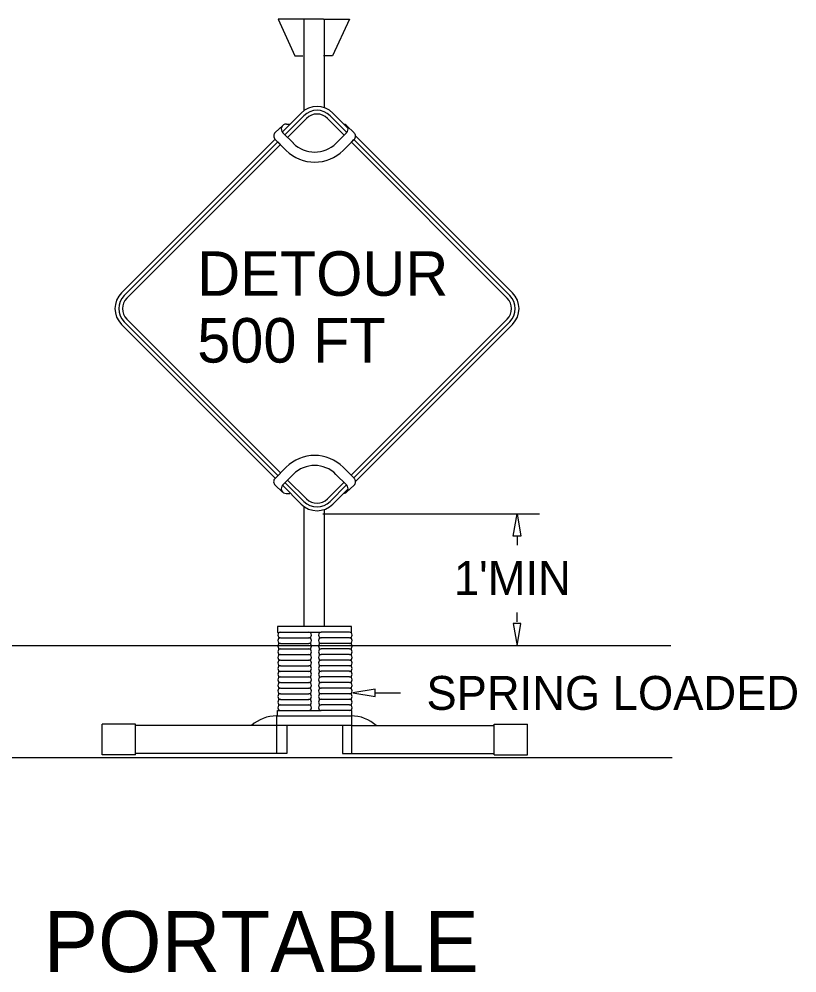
# Model space of a CAD drawing. Extents: x 12.65 to 19.62, y 5.94 to 15.74.
# Drawn here: x 14.024 to 15.401, y 12.626 to 14.315 of the extents above; entities that cross this region are included whole.
import ezdxf

# ---------------------------------------------------------------- set-up
doc = ezdxf.new("R2010")
doc.units = 0
for name, color, linetype in [('DETL-DIMS', 7, 'Continuous'), ('DETL-LINE', 7, 'Continuous'), ('DETL-NOTE', 7, 'Continuous'), ('DETL-TITL', 7, 'Continuous')]:
    doc.layers.add(name, color=color, linetype=linetype)

msp = doc.modelspace()

# ---------------------------------------------------------------- linework, layer by layer
at = {"layer": 'DETL-DIMS'}
for p, q in [((14.5617, 13.4389), (14.9454, 13.4389)), ((14.9058, 13.3993), (14.9058, 13.383)), ((14.9058, 13.2478), (14.9058, 13.2642)), ((14.6548, 13.1218), (14.6994, 13.1218))]:
    msp.add_line(p, q, dxfattribs=at)
for points in [[(14.9124, 13.3993), (14.8992, 13.3993), (14.9058, 13.4389)], [(14.9124, 13.2445), (14.8992, 13.2445), (14.9058, 13.2049)], [(14.6548, 13.1152), (14.6548, 13.1284), (14.6152, 13.1218)]]:
    msp.add_lwpolyline(points, close=True, dxfattribs=at)
at = {"layer": 'DETL-LINE'}
for p, q in [((14.5286, 14.3146), (14.4826, 14.3146)), ((14.4826, 14.3146), (14.5124, 14.2494)), ((14.5629, 14.3146), (14.5266, 14.3146)), ((14.5286, 14.1523), (14.5286, 14.3146)), ((14.5629, 14.3146), (14.609, 14.3146)), ((14.5649, 14.1574), (14.5649, 14.3146)), ((14.609, 14.3146), (14.5791, 14.2494)), ((14.5124, 14.2494), (14.5266, 14.2494)), ((14.5791, 14.2494), (14.5629, 14.2494)), ((14.5235, 14.1481), (14.4901, 14.1145)), ((14.5282, 14.1434), (14.4947, 14.1098)), ((14.4993, 14.1051), (14.5329, 14.1386)), ((14.5703, 14.1387), (14.5703, 14.1386)), ((14.5703, 14.1386), (14.5997, 14.1092)), ((14.6044, 14.1139), (14.575, 14.1434)), ((14.6066, 14.1211), (14.5797, 14.1481)), ((14.4909, 14.1261), (14.4777, 14.1138)), ((14.4973, 14.1287), (14.5043, 14.1287)), ((14.6047, 14.1255), (14.6173, 14.1135)), ((14.4774, 14.1019), (14.2056, 13.83)), ((14.4971, 14.0821), (14.4775, 14.1017)), ((14.5097, 14.0947), (14.491, 14.1135)), ((14.6041, 14.1135), (14.5853, 14.0947)), ((14.6173, 14.1016), (14.5979, 14.0821)), ((14.6124, 14.0966), (14.6171, 14.1013)), ((14.8929, 13.8253), (14.6171, 14.1013)), ((14.6171, 14.1013), (14.8929, 13.8253)), ((14.8929, 13.8253), (14.6171, 14.1013)), ((14.6171, 14.1013), (14.8929, 13.8253)), ((14.6171, 14.1013), (14.8929, 13.8253)), ((14.8976, 13.83), (14.6198, 14.1079)), ((14.2103, 13.8253), (14.4821, 14.0972)), ((14.4867, 14.0925), (14.2149, 13.8207)), ((14.4821, 14.0972), (14.4867, 14.0925)), ((14.8883, 13.8207), (14.6124, 14.0966)), ((14.6124, 14.0966), (14.8883, 13.8207)), ((14.8883, 13.8207), (14.6124, 14.0966)), ((14.6124, 14.0966), (14.8883, 13.8207)), ((14.8883, 13.8207), (14.6124, 14.0966)), ((14.487, 13.5112), (14.2149, 13.7833)), ((14.6121, 13.5071), (14.8883, 13.7833)), ((14.8883, 13.7833), (14.6121, 13.5071)), ((14.6121, 13.5071), (14.8883, 13.7833)), ((14.8883, 13.7833), (14.6121, 13.5071)), ((14.6121, 13.5071), (14.8883, 13.7833)), ((14.8883, 13.7833), (14.8883, 13.7833)), ((14.2056, 13.7739), (14.4776, 13.5019)), ((14.2102, 13.7786), (14.2103, 13.7786)), ((14.2103, 13.7786), (14.4823, 13.5065)), ((14.6167, 13.5024), (14.8929, 13.7786)), ((14.8929, 13.7786), (14.6167, 13.5024)), ((14.8929, 13.7786), (14.6167, 13.5024)), ((14.62, 13.4962), (14.8976, 13.7739)), ((14.497, 13.5212), (14.4773, 13.5015)), ((14.6175, 13.5016), (14.5978, 13.5212)), ((14.5096, 13.5086), (14.4909, 13.4899)), ((14.4949, 13.4939), (14.5282, 13.4606)), ((14.5329, 13.4653), (14.4996, 13.4986)), ((14.5995, 13.4945), (14.5703, 13.4653)), ((14.6039, 13.4899), (14.5852, 13.5086)), ((14.4908, 13.4769), (14.4775, 13.4895)), ((14.4903, 13.4892), (14.5235, 13.4559)), ((14.575, 13.4606), (14.6041, 13.4898)), ((14.5797, 13.4559), (14.6066, 13.4829)), ((14.6037, 13.4769), (14.6173, 13.4895)), ((14.4972, 13.4747), (14.5034, 13.4747)), ((14.5329, 13.4653), (14.5329, 13.4653)), ((14.5286, 13.2384), (14.5286, 13.4516)), ((14.5649, 13.2384), (14.5649, 13.4466)), ((14.6125, 13.239), (14.4819, 13.239)), ((14.4819, 13.239), (14.4819, 13.2289)), ((14.4819, 13.2289), (14.4872, 13.2291)), ((14.4872, 13.2291), (14.537, 13.2291)), ((14.537, 13.2291), (14.5592, 13.2291)), ((14.609, 13.2291), (14.5592, 13.2291)), ((14.6125, 13.2289), (14.609, 13.2291)), ((14.6125, 13.2289), (14.6125, 13.239)), ((13.0783, 13.2055), (15.1784, 13.2055)), ((14.4872, 13.2193), (14.537, 13.2193)), ((14.4872, 13.2093), (14.537, 13.2093)), ((14.609, 13.2193), (14.5592, 13.2193)), ((14.609, 13.2093), (14.5592, 13.2093)), ((14.9058, 13.2082), (14.9058, 13.2082)), ((14.9058, 13.2082), (14.9058, 13.2082)), ((14.4872, 13.1995), (14.537, 13.1995)), ((14.4872, 13.1895), (14.537, 13.1895)), ((14.609, 13.1995), (14.5592, 13.1995)), ((14.609, 13.1895), (14.5592, 13.1895)), ((14.4872, 13.1797), (14.537, 13.1797)), ((14.609, 13.1797), (14.5592, 13.1797)), ((14.4872, 13.1697), (14.537, 13.1697)), ((14.4872, 13.1599), (14.537, 13.1599)), ((14.609, 13.1697), (14.5592, 13.1697)), ((14.609, 13.1599), (14.5592, 13.1599)), ((14.4872, 13.1499), (14.537, 13.1499)), ((14.4872, 13.1401), (14.537, 13.1401)), ((14.609, 13.1499), (14.5592, 13.1499)), ((14.609, 13.1401), (14.5592, 13.1401)), ((14.4872, 13.1301), (14.537, 13.1301)), ((14.609, 13.1301), (14.5592, 13.1301)), ((14.4872, 13.1203), (14.537, 13.1203)), ((14.4872, 13.1103), (14.537, 13.1103)), ((14.609, 13.1203), (14.5592, 13.1203)), ((14.609, 13.1103), (14.5592, 13.1103)), ((14.4815, 13.0904), (14.4872, 13.0905)), ((14.4815, 13.0807), (14.4815, 13.0904)), ((14.4872, 13.1005), (14.537, 13.1005)), ((14.4872, 13.0905), (14.537, 13.0905)), ((14.537, 13.0905), (14.5592, 13.0905)), ((14.609, 13.1005), (14.5592, 13.1005)), ((14.609, 13.0905), (14.5592, 13.0905)), ((14.6129, 13.0904), (14.609, 13.0905)), ((14.6129, 13.0904), (14.6129, 13.0807)), ((14.48, 13.0809), (14.612, 13.0809)), ((14.48, 13.0809), (14.48, 13.0644)), ((14.6129, 13.0807), (14.4815, 13.0807)), ((14.6125, 13.0806), (14.6125, 13.064)), ((14.2302, 13.0662), (14.1713, 13.0662)), ((14.1713, 13.012), (14.1713, 13.0662)), ((14.2302, 13.012), (14.2302, 13.0662)), ((14.4831, 13.064), (14.2302, 13.064)), ((14.48, 13.0644), (14.612, 13.0644)), ((14.48, 13.0644), (14.48, 13.0142)), ((14.4981, 13.064), (14.4981, 13.0142)), ((14.5967, 13.064), (14.5967, 13.0142)), ((14.6125, 13.064), (14.8654, 13.064)), ((14.6125, 13.064), (14.6125, 13.0142)), ((14.8654, 13.0662), (14.9244, 13.0662)), ((14.8654, 13.012), (14.8654, 13.0662)), ((14.9244, 13.012), (14.9244, 13.0662)), ((15.1805, 13.0067), (13.8687, 13.0067)), ((14.2302, 13.012), (14.1713, 13.012)), ((14.4981, 13.0142), (14.2302, 13.0142)), ((14.5967, 13.0142), (14.8654, 13.0142)), ((14.8654, 13.012), (14.9244, 13.012))]:
    msp.add_line(p, q, dxfattribs=at)
for centre, radius, start, end in [((14.5516, 14.12), 0.0397, 45, 135), ((14.5516, 14.12), 0.0331, 45, 135), ((14.5516, 14.12), 0.0265, 45, 135), ((14.4973, 14.1198), 0.00891, 90, 225.0258), ((14.5978, 14.1198), 0.00891, 314.9742, 81.781), ((14.4834, 14.1077), 0.00836, 132.9298, 225.0258), ((14.6114, 14.1075), 0.00836, 314.9742, 46.0534), ((14.5475, 14.1326), 0.0535, 225.0258, 314.9742), ((14.5475, 14.1326), 0.0713, 225.0258, 314.9742), ((14.2336, 13.802), 0.0397, 135, 225), ((14.2336, 13.802), 0.0331, 135, 225), ((14.2336, 13.802), 0.0265, 135, 225), ((14.8696, 13.802), 0.0265, 315, 45), ((14.8696, 13.802), 0.0331, 315, 45), ((14.8696, 13.802), 0.0397, 315, 45), ((14.5474, 13.4708), 0.0713, 45.0258, 134.9742), ((14.5474, 13.4708), 0.0535, 45.0258, 134.9742), ((14.4832, 13.4956), 0.00836, 134.9742, 226.7296), ((14.6116, 13.4956), 0.00836, 312.6558, 45.0258), ((14.4972, 13.4836), 0.00891, 134.9742, 270), ((14.5977, 13.4836), 0.00891, 270, 45.0258), ((14.5516, 13.484), 0.0331, 225, 315), ((14.5516, 13.484), 0.0265, 225, 315), ((14.5516, 13.484), 0.0397, 225, 315), ((14.4872, 13.2242), 0.00495, 90, 270), ((14.537, 13.2242), 0.00495, 270.0001, 89.9999), ((14.5592, 13.2242), 0.00495, 90.0001, 269.9999), ((14.609, 13.2242), 0.00495, 270, 90), ((14.4872, 13.2143), 0.00495, 90, 270), ((14.4872, 13.2044), 0.00495, 90, 270), ((14.537, 13.2143), 0.00495, 270.0001, 89.9999), ((14.537, 13.2044), 0.00495, 270.0001, 89.9999), ((14.5592, 13.2143), 0.00495, 90.0001, 269.9999), ((14.5592, 13.2044), 0.00495, 90.0001, 269.9999), ((14.609, 13.2143), 0.00495, 270, 90), ((14.609, 13.2044), 0.00495, 270, 90), ((14.4872, 13.1945), 0.00495, 90, 270), ((14.4872, 13.1846), 0.00495, 90, 270), ((14.537, 13.1945), 0.00495, 270.0001, 89.9999), ((14.537, 13.1846), 0.00495, 270.0001, 89.9999), ((14.5592, 13.1945), 0.00495, 90.0001, 269.9999), ((14.5592, 13.1846), 0.00495, 90.0001, 269.9999), ((14.609, 13.1945), 0.00495, 270, 90), ((14.609, 13.1846), 0.00495, 270, 90), ((14.4872, 13.1747), 0.00495, 90, 270), ((14.537, 13.1747), 0.00495, 270.0001, 89.9999), ((14.5592, 13.1747), 0.00495, 90.0001, 269.9999), ((14.609, 13.1747), 0.00495, 270, 90), ((14.4872, 13.1648), 0.00495, 90, 270), ((14.4872, 13.1549), 0.00495, 90, 270), ((14.537, 13.1648), 0.00495, 270.0001, 89.9999), ((14.537, 13.1549), 0.00495, 270.0001, 89.9999), ((14.5592, 13.1648), 0.00495, 90.0001, 269.9999), ((14.5592, 13.1549), 0.00495, 90.0001, 269.9999), ((14.609, 13.1648), 0.00495, 270, 90), ((14.609, 13.1549), 0.00495, 270, 90), ((14.4872, 13.145), 0.00495, 90, 270), ((14.4872, 13.1351), 0.00495, 90, 270), ((14.537, 13.145), 0.00495, 270.0001, 89.9999), ((14.537, 13.1351), 0.00495, 270.0001, 89.9999), ((14.5592, 13.145), 0.00495, 90.0001, 269.9999), ((14.5592, 13.1351), 0.00495, 90.0001, 269.9999), ((14.609, 13.145), 0.00495, 270, 90), ((14.609, 13.1351), 0.00495, 270, 90), ((14.4872, 13.1252), 0.00495, 90, 270), ((14.537, 13.1252), 0.00495, 270.0001, 89.9999), ((14.5592, 13.1252), 0.00495, 90.0001, 269.9999), ((14.609, 13.1252), 0.00495, 270, 90), ((14.4872, 13.1153), 0.00495, 90, 270), ((14.4872, 13.1054), 0.00495, 90, 270), ((14.537, 13.1153), 0.00495, 270.0001, 89.9999), ((14.537, 13.1054), 0.00495, 270.0001, 89.9999), ((14.5592, 13.1153), 0.00495, 90.0001, 269.9999), ((14.5592, 13.1054), 0.00495, 90.0001, 269.9999), ((14.609, 13.1153), 0.00495, 270, 90), ((14.609, 13.1054), 0.00495, 270, 90), ((14.4872, 13.0955), 0.00495, 90, 270), ((14.537, 13.0955), 0.00495, 270.0001, 89.9999), ((14.5592, 13.0955), 0.00495, 90.0001, 269.9999), ((14.609, 13.0955), 0.00495, 270, 90), ((14.48, 13.015), 0.066, 90, 132.0559), ((14.612, 13.015), 0.066, 47.5898, 90)]:
    msp.add_arc(centre, radius, start, end, dxfattribs=at)

# ---------------------------------------------------------------- texts
for s, p in [('DETOUR', (14.3395, 13.8247)), ('500 FT', (14.3395, 13.7065))]:
    msp.add_text(s, height=0.07876, rotation=360, dxfattribs=at).set_placement(p)
at = {"layer": 'DETL-NOTE'}
for s, p in [("1'MIN", (14.794, 13.2951)), ('SPRING LOADED', (14.7454, 13.0917))]:
    msp.add_text(s, height=0.06, rotation=360, dxfattribs=at).set_placement(p)
at = {"layer": 'DETL-TITL'}
msp.add_text('PORTABLE', height=0.108, rotation=360, dxfattribs=at).set_placement((14.0676, 12.6275))

doc.saveas('drawing.dxf')
